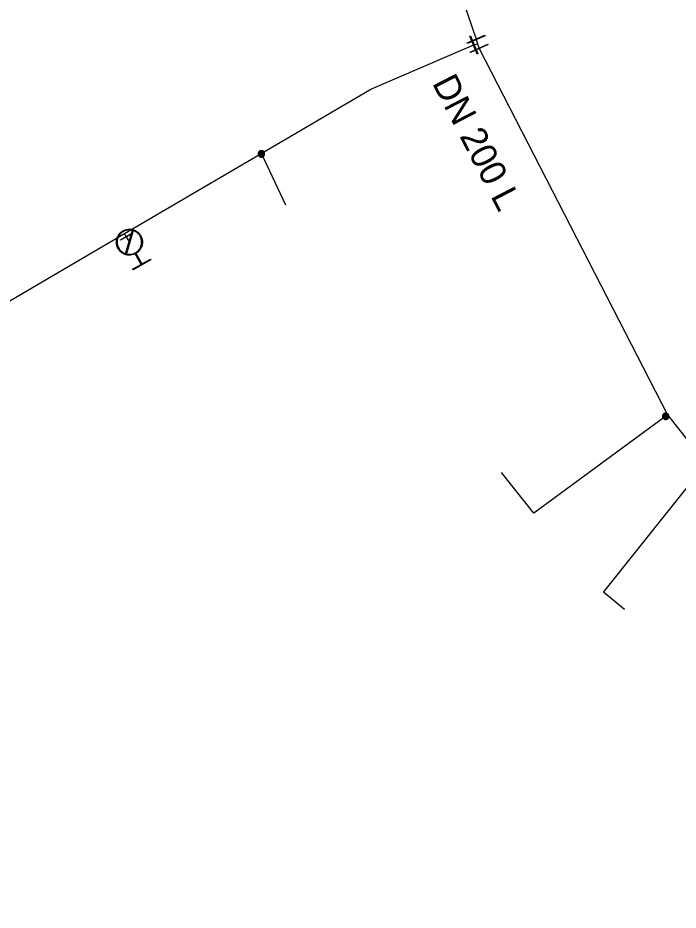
# Model space of a CAD drawing. Extents: x -832382 to -831581, y -1074670 to -1074251.
# Drawn here: x -831734.8 to -831683.8, y -1074502.9 to -1074434.1 of the extents above; entities that cross this region are included whole.
import ezdxf

# ---------------------------------------------------------------- set-up
doc = ezdxf.new("R2010")
doc.units = 0
for name, color, linetype in [('Hyd-odbočka', 7, 'Continuous'), ('Hyd-šoupě', 7, 'Continuous'), ('Hydrant', 7, 'Continuous'), ('Přípojka vodovodu', 7, 'Continuous'), ('Přípojkový uzávěr', 7, 'Continuous'), ('Roz-řad', 7, 'Continuous'), ('Roz-řad-popis základní', 7, 'Continuous'), ('Řad-šoupě', 7, 'Continuous')]:
    doc.layers.add(name, color=color, linetype=linetype)

msp = doc.modelspace()

# ---------------------------------------------------------------- linework, layer by layer
at = {"layer": 'Hyd-odbočka'}
for q in [(-831726.547, -1074450.718), (-831726.16, -1074451.38)]:
    msp.add_line((-831726.41, -1074450.96), q, dxfattribs=at)
at = {"layer": 'Hyd-šoupě'}
msp.add_lwpolyline([(-831726.853, -1074451.192), (-831725.982, -1074450.7), (-831725.967, -1074450.727), (-831726.837, -1074451.219), (-831726.853, -1074451.192)], dxfattribs=at)
at = {"layer": 'Hydrant'}
for points in [[(-831726.451, -1074452.273), (-831725.928, -1074450.468)], [(-831725.869, -1074450.487), (-831726.393, -1074452.29)], [(-831725.651, -1074452.241), (-831725.199, -1074453.063), (-831724.542, -1074452.702), (-831724.512, -1074452.756), (-831725.881, -1074453.509), (-831725.911, -1074453.454), (-831725.254, -1074453.093), (-831725.706, -1074452.271)]]:
    msp.add_lwpolyline(points, dxfattribs=at)
for points in [[(-831725.706, -1074452.271), (-831725.917, -1074452.378), (-831726.172, -1074452.38), (-831726.443, -1074452.382), (-831726.676, -1074452.237), (-831726.91, -1074452.091), (-831727.036, -1074451.862), (-831727.161, -1074451.634), (-831727.161, -1074451.362), (-831727.16, -1074451.089), (-831727.015, -1074450.859), (-831726.869, -1074450.629), (-831726.642, -1074450.504), (-831726.414, -1074450.379), (-831726.142, -1074450.379), (-831725.869, -1074450.38), (-831725.639, -1074450.525), (-831725.409, -1074450.671), (-831725.284, -1074450.898), (-831725.158, -1074451.128), (-831725.16, -1074451.403), (-831725.162, -1074451.679), (-831725.309, -1074451.906), (-831725.446, -1074452.12), (-831725.651, -1074452.241)], [(-831725.928, -1074450.468), (-831726.031, -1074450.442), (-831726.142, -1074450.443), (-831726.398, -1074450.441), (-831726.612, -1074450.558), (-831726.826, -1074450.676), (-831726.962, -1074450.892), (-831727.098, -1074451.109), (-831727.099, -1074451.363), (-831727.099, -1074451.618), (-831726.982, -1074451.832), (-831726.863, -1074452.047), (-831726.644, -1074452.183), (-831726.55, -1074452.24), (-831726.451, -1074452.273)], [(-831726.393, -1074452.29), (-831726.284, -1074452.318), (-831726.171, -1074452.317), (-831725.916, -1074452.315), (-831725.708, -1074452.202), (-831725.501, -1074452.088), (-831725.363, -1074451.873), (-831725.224, -1074451.659), (-831725.222, -1074451.402), (-831725.22, -1074451.144), (-831725.338, -1074450.928), (-831725.456, -1074450.714), (-831725.673, -1074450.58), (-831725.766, -1074450.519), (-831725.869, -1074450.487)]]:
    msp.add_open_spline(points, degree=3, dxfattribs=at)
at = {"layer": 'Přípojka vodovodu'}
for points in [[(-831715.985, -1074444.538), (-831715.97, -1074444.57), (-831714.12, -1074448.5)], [(-831684.613, -1074464.713), (-831684.753, -1074464.816), (-831694.927, -1074472.301), (-831697.436, -1074469.153)], [(-831681.645, -1074468.448), (-831681.71, -1074468.53), (-831689.553, -1074478.367), (-831687.925, -1074479.696)]]:
    msp.add_lwpolyline(points, dxfattribs=at)
at = {"layer": 'Přípojkový uzávěr'}
for points in [[(-831715.97, -1074444.32), (-831715.907, -1074444.32), (-831715.847, -1074444.352), (-831715.788, -1074444.384), (-831715.754, -1074444.445), (-831715.72, -1074444.505), (-831715.72, -1074444.57), (-831715.72, -1074444.635), (-831715.753, -1074444.695), (-831715.786, -1074444.754), (-831715.845, -1074444.787), (-831715.905, -1074444.82), (-831715.97, -1074444.82), (-831716.035, -1074444.82), (-831716.095, -1074444.787), (-831716.154, -1074444.754), (-831716.187, -1074444.695), (-831716.22, -1074444.635), (-831716.22, -1074444.57), (-831716.22, -1074444.505), (-831716.186, -1074444.445), (-831716.153, -1074444.384), (-831716.093, -1074444.352), (-831716.033, -1074444.32), (-831715.97, -1074444.32)], [(-831715.97, -1074444.343), (-831716.027, -1074444.343), (-831716.082, -1074444.373), (-831716.136, -1074444.402), (-831716.166, -1074444.456), (-831716.197, -1074444.511), (-831716.197, -1074444.57), (-831716.197, -1074444.629), (-831716.167, -1074444.683), (-831716.137, -1074444.737), (-831716.083, -1074444.767), (-831716.029, -1074444.797), (-831715.97, -1074444.797), (-831715.911, -1074444.797), (-831715.857, -1074444.767), (-831715.803, -1074444.737), (-831715.773, -1074444.683), (-831715.743, -1074444.629), (-831715.743, -1074444.57), (-831715.743, -1074444.511), (-831715.774, -1074444.456), (-831715.805, -1074444.402), (-831715.859, -1074444.373), (-831715.913, -1074444.343), (-831715.97, -1074444.343)], [(-831715.97, -1074444.361), (-831715.917, -1074444.361), (-831715.867, -1074444.388), (-831715.817, -1074444.414), (-831715.789, -1074444.465), (-831715.761, -1074444.515), (-831715.761, -1074444.57), (-831715.761, -1074444.625), (-831715.788, -1074444.674), (-831715.815, -1074444.724), (-831715.866, -1074444.752), (-831715.916, -1074444.779), (-831715.97, -1074444.779), (-831716.024, -1074444.779), (-831716.074, -1074444.752), (-831716.125, -1074444.724), (-831716.152, -1074444.674), (-831716.179, -1074444.625), (-831716.179, -1074444.57), (-831716.179, -1074444.515), (-831716.151, -1074444.465), (-831716.123, -1074444.414), (-831716.073, -1074444.388), (-831716.023, -1074444.361), (-831715.97, -1074444.361)], [(-831715.97, -1074444.383), (-831716.049, -1074444.383), (-831716.103, -1074444.437), (-831716.157, -1074444.492), (-831716.157, -1074444.57), (-831716.157, -1074444.648), (-831716.103, -1074444.703), (-831716.048, -1074444.758), (-831715.97, -1074444.758), (-831715.892, -1074444.758), (-831715.837, -1074444.703), (-831715.782, -1074444.648), (-831715.782, -1074444.57), (-831715.782, -1074444.492), (-831715.837, -1074444.437), (-831715.892, -1074444.383), (-831715.97, -1074444.383)], [(-831715.97, -1074444.405), (-831715.902, -1074444.405), (-831715.854, -1074444.453), (-831715.806, -1074444.501), (-831715.806, -1074444.57), (-831715.806, -1074444.638), (-831715.854, -1074444.686), (-831715.902, -1074444.734), (-831715.97, -1074444.734), (-831716.039, -1074444.734), (-831716.087, -1074444.686), (-831716.135, -1074444.638), (-831716.135, -1074444.57), (-831716.135, -1074444.501), (-831716.087, -1074444.453), (-831716.039, -1074444.405), (-831715.97, -1074444.405)], [(-831715.97, -1074444.425), (-831716.031, -1074444.425), (-831716.073, -1074444.467), (-831716.115, -1074444.51), (-831716.115, -1074444.57), (-831716.115, -1074444.629), (-831716.073, -1074444.672), (-831716.031, -1074444.714), (-831715.97, -1074444.714), (-831715.911, -1074444.714), (-831715.868, -1074444.672), (-831715.826, -1074444.629), (-831715.826, -1074444.57), (-831715.826, -1074444.51), (-831715.868, -1074444.467), (-831715.91, -1074444.425), (-831715.97, -1074444.425)], [(-831715.97, -1074444.445), (-831715.918, -1074444.445), (-831715.881, -1074444.482), (-831715.845, -1074444.518), (-831715.845, -1074444.57), (-831715.845, -1074444.622), (-831715.882, -1074444.659), (-831715.918, -1074444.695), (-831715.97, -1074444.695), (-831716.022, -1074444.695), (-831716.058, -1074444.659), (-831716.095, -1074444.622), (-831716.095, -1074444.57), (-831716.095, -1074444.518), (-831716.059, -1074444.482), (-831716.022, -1074444.445), (-831715.97, -1074444.445)], [(-831715.97, -1074444.468), (-831716.012, -1074444.468), (-831716.042, -1074444.498), (-831716.072, -1074444.528), (-831716.072, -1074444.57), (-831716.072, -1074444.612), (-831716.042, -1074444.642), (-831716.012, -1074444.671), (-831715.97, -1074444.671), (-831715.928, -1074444.671), (-831715.898, -1074444.642), (-831715.869, -1074444.612), (-831715.869, -1074444.57), (-831715.869, -1074444.528), (-831715.898, -1074444.498), (-831715.928, -1074444.468), (-831715.97, -1074444.468)], [(-831715.97, -1074444.486), (-831715.935, -1074444.486), (-831715.911, -1074444.51), (-831715.886, -1074444.535), (-831715.886, -1074444.57), (-831715.886, -1074444.605), (-831715.911, -1074444.629), (-831715.935, -1074444.654), (-831715.97, -1074444.654), (-831716.005, -1074444.654), (-831716.03, -1074444.629), (-831716.054, -1074444.605), (-831716.054, -1074444.57), (-831716.054, -1074444.535), (-831716.03, -1074444.51), (-831716.005, -1074444.486), (-831715.97, -1074444.486)], [(-831715.97, -1074444.508), (-831715.996, -1074444.508), (-831716.014, -1074444.526), (-831716.032, -1074444.544), (-831716.032, -1074444.57), (-831716.032, -1074444.596), (-831716.014, -1074444.614), (-831715.996, -1074444.633), (-831715.97, -1074444.633), (-831715.944, -1074444.633), (-831715.926, -1074444.614), (-831715.907, -1074444.596), (-831715.907, -1074444.57), (-831715.907, -1074444.544), (-831715.926, -1074444.526), (-831715.944, -1074444.508), (-831715.97, -1074444.508)], [(-831715.97, -1074444.531), (-831715.954, -1074444.531), (-831715.942, -1074444.542), (-831715.931, -1074444.553), (-831715.931, -1074444.57), (-831715.931, -1074444.586), (-831715.942, -1074444.598), (-831715.954, -1074444.609), (-831715.97, -1074444.609), (-831715.986, -1074444.609), (-831715.998, -1074444.598), (-831716.009, -1074444.586), (-831716.009, -1074444.57), (-831716.009, -1074444.553), (-831715.998, -1074444.542), (-831715.986, -1074444.531), (-831715.97, -1074444.531)], [(-831715.97, -1074444.547), (-831715.98, -1074444.547), (-831715.987, -1074444.553), (-831715.994, -1074444.56), (-831715.994, -1074444.57), (-831715.994, -1074444.58), (-831715.987, -1074444.587), (-831715.98, -1074444.593), (-831715.97, -1074444.593), (-831715.96, -1074444.593), (-831715.954, -1074444.587), (-831715.947, -1074444.58), (-831715.947, -1074444.57), (-831715.947, -1074444.56), (-831715.954, -1074444.553), (-831715.96, -1074444.547), (-831715.97, -1074444.547)], [(-831684.753, -1074464.566), (-831684.69, -1074464.566), (-831684.63, -1074464.598), (-831684.571, -1074464.631), (-831684.537, -1074464.691), (-831684.503, -1074464.751), (-831684.503, -1074464.816), (-831684.503, -1074464.881), (-831684.536, -1074464.941), (-831684.569, -1074465), (-831684.629, -1074465.033), (-831684.688, -1074465.066), (-831684.753, -1074465.066), (-831684.818, -1074465.066), (-831684.878, -1074465.033), (-831684.937, -1074465), (-831684.97, -1074464.941), (-831685.003, -1074464.881), (-831685.003, -1074464.816), (-831685.003, -1074464.751), (-831684.969, -1074464.691), (-831684.936, -1074464.631), (-831684.876, -1074464.598), (-831684.816, -1074464.566), (-831684.753, -1074464.566)], [(-831684.753, -1074464.59), (-831684.81, -1074464.59), (-831684.865, -1074464.619), (-831684.919, -1074464.648), (-831684.949, -1074464.703), (-831684.98, -1074464.757), (-831684.98, -1074464.816), (-831684.98, -1074464.875), (-831684.95, -1074464.929), (-831684.92, -1074464.983), (-831684.866, -1074465.013), (-831684.812, -1074465.043), (-831684.753, -1074465.043), (-831684.694, -1074465.043), (-831684.64, -1074465.013), (-831684.586, -1074464.983), (-831684.556, -1074464.929), (-831684.526, -1074464.875), (-831684.526, -1074464.816), (-831684.526, -1074464.757), (-831684.557, -1074464.703), (-831684.588, -1074464.648), (-831684.642, -1074464.619), (-831684.696, -1074464.59), (-831684.753, -1074464.59)], [(-831684.753, -1074464.607), (-831684.7, -1074464.607), (-831684.65, -1074464.634), (-831684.6, -1074464.661), (-831684.572, -1074464.711), (-831684.544, -1074464.762), (-831684.544, -1074464.816), (-831684.544, -1074464.871), (-831684.571, -1074464.921), (-831684.598, -1074464.971), (-831684.649, -1074464.998), (-831684.699, -1074465.026), (-831684.753, -1074465.026), (-831684.807, -1074465.026), (-831684.858, -1074464.998), (-831684.908, -1074464.971), (-831684.935, -1074464.921), (-831684.962, -1074464.871), (-831684.962, -1074464.816), (-831684.962, -1074464.762), (-831684.934, -1074464.711), (-831684.906, -1074464.661), (-831684.856, -1074464.634), (-831684.806, -1074464.607), (-831684.753, -1074464.607)], [(-831684.754, -1074464.629), (-831684.832, -1074464.629), (-831684.886, -1074464.684), (-831684.941, -1074464.739), (-831684.941, -1074464.816), (-831684.941, -1074464.894), (-831684.886, -1074464.949), (-831684.831, -1074465.004), (-831684.754, -1074465.004), (-831684.675, -1074465.004), (-831684.62, -1074464.949), (-831684.566, -1074464.894), (-831684.566, -1074464.816), (-831684.566, -1074464.739), (-831684.62, -1074464.684), (-831684.675, -1074464.629), (-831684.754, -1074464.629)], [(-831684.754, -1074464.652), (-831684.685, -1074464.652), (-831684.637, -1074464.7), (-831684.589, -1074464.748), (-831684.589, -1074464.816), (-831684.589, -1074464.884), (-831684.637, -1074464.932), (-831684.685, -1074464.98), (-831684.754, -1074464.98), (-831684.822, -1074464.98), (-831684.87, -1074464.932), (-831684.918, -1074464.884), (-831684.918, -1074464.816), (-831684.918, -1074464.748), (-831684.87, -1074464.7), (-831684.822, -1074464.652), (-831684.754, -1074464.652)], [(-831684.754, -1074464.671), (-831684.814, -1074464.671), (-831684.856, -1074464.714), (-831684.898, -1074464.756), (-831684.898, -1074464.816), (-831684.898, -1074464.876), (-831684.856, -1074464.918), (-831684.814, -1074464.96), (-831684.754, -1074464.96), (-831684.694, -1074464.96), (-831684.651, -1074464.918), (-831684.609, -1074464.876), (-831684.609, -1074464.816), (-831684.609, -1074464.756), (-831684.651, -1074464.714), (-831684.693, -1074464.671), (-831684.754, -1074464.671)], [(-831684.753, -1074464.691), (-831684.701, -1074464.691), (-831684.664, -1074464.728), (-831684.628, -1074464.764), (-831684.628, -1074464.816), (-831684.628, -1074464.868), (-831684.665, -1074464.905), (-831684.701, -1074464.941), (-831684.753, -1074464.941), (-831684.805, -1074464.941), (-831684.841, -1074464.905), (-831684.878, -1074464.868), (-831684.878, -1074464.816), (-831684.878, -1074464.764), (-831684.842, -1074464.728), (-831684.806, -1074464.691), (-831684.753, -1074464.691)], [(-831684.753, -1074464.714), (-831684.796, -1074464.714), (-831684.825, -1074464.744), (-831684.855, -1074464.774), (-831684.855, -1074464.816), (-831684.855, -1074464.858), (-831684.825, -1074464.888), (-831684.796, -1074464.918), (-831684.753, -1074464.918), (-831684.711, -1074464.918), (-831684.681, -1074464.888), (-831684.652, -1074464.858), (-831684.652, -1074464.816), (-831684.652, -1074464.774), (-831684.681, -1074464.744), (-831684.711, -1074464.714), (-831684.753, -1074464.714)], [(-831684.753, -1074464.732), (-831684.718, -1074464.732), (-831684.694, -1074464.756), (-831684.669, -1074464.781), (-831684.669, -1074464.816), (-831684.669, -1074464.851), (-831684.694, -1074464.876), (-831684.718, -1074464.9), (-831684.753, -1074464.9), (-831684.788, -1074464.9), (-831684.813, -1074464.876), (-831684.837, -1074464.851), (-831684.837, -1074464.816), (-831684.837, -1074464.781), (-831684.813, -1074464.756), (-831684.788, -1074464.732), (-831684.753, -1074464.732)], [(-831684.753, -1074464.754), (-831684.779, -1074464.754), (-831684.797, -1074464.772), (-831684.816, -1074464.79), (-831684.816, -1074464.816), (-831684.816, -1074464.842), (-831684.797, -1074464.86), (-831684.779, -1074464.879), (-831684.753, -1074464.879), (-831684.727, -1074464.879), (-831684.709, -1074464.86), (-831684.691, -1074464.842), (-831684.691, -1074464.816), (-831684.691, -1074464.79), (-831684.709, -1074464.772), (-831684.727, -1074464.754), (-831684.753, -1074464.754)], [(-831684.753, -1074464.777), (-831684.737, -1074464.777), (-831684.725, -1074464.788), (-831684.714, -1074464.8), (-831684.714, -1074464.816), (-831684.714, -1074464.832), (-831684.725, -1074464.844), (-831684.737, -1074464.855), (-831684.753, -1074464.855), (-831684.769, -1074464.855), (-831684.781, -1074464.844), (-831684.792, -1074464.832), (-831684.792, -1074464.816), (-831684.792, -1074464.8), (-831684.781, -1074464.788), (-831684.769, -1074464.777), (-831684.753, -1074464.777)], [(-831684.753, -1074464.793), (-831684.763, -1074464.793), (-831684.77, -1074464.799), (-831684.777, -1074464.806), (-831684.777, -1074464.816), (-831684.777, -1074464.826), (-831684.77, -1074464.833), (-831684.763, -1074464.84), (-831684.753, -1074464.84), (-831684.743, -1074464.84), (-831684.737, -1074464.833), (-831684.73, -1074464.826), (-831684.73, -1074464.816), (-831684.73, -1074464.806), (-831684.737, -1074464.799), (-831684.743, -1074464.793), (-831684.753, -1074464.793)]]:
    msp.add_open_spline(points, degree=3, dxfattribs=at)
at = {"layer": 'Roz-řad'}
for p, q in [((-831699.39, -1074435.73), (-831699.275, -1074436.08)), ((-831699.57, -1074436.17), (-831699.275, -1074436.08)), ((-831699.275, -1074436.08), (-831699.16, -1074436.43))]:
    msp.add_line(p, q, dxfattribs=at)
for points in [[(-831710.74, -1074402.57), (-831709.938, -1074404.913), (-831709.653, -1074405.745), (-831699.39, -1074435.73)], [(-831778.085, -1074503.291), (-831772.842, -1074496.164), (-831771.36, -1074494.15), (-831763.76, -1074483.99), (-831763.769, -1074484.049), (-831763.194, -1074483.398), (-831747.84, -1074465.99), (-831737.66, -1074457.22), (-831726.547, -1074450.718), (-831715.985, -1074444.538), (-831707.51, -1074439.58), (-831699.57, -1074436.17)], [(-831699.16, -1074436.43), (-831684.613, -1074464.713), (-831681.645, -1074468.448), (-831680.42, -1074469.611), (-831670.1, -1074478.783)]]:
    msp.add_lwpolyline(points, dxfattribs=at)
at = {"layer": 'Řad-šoupě'}
for points in [[(-831698.693, -1074435.453), (-831700.069, -1074436.05), (-831700.088, -1074436.007), (-831698.712, -1074435.41), (-831698.693, -1074435.453)], [(-831699.314, -1074436.875), (-831699.87, -1074435.482), (-831699.827, -1074435.465), (-831699.27, -1074436.858), (-831699.314, -1074436.875)], [(-831699.854, -1074436.717), (-831698.486, -1074436.101), (-831698.467, -1074436.144), (-831699.834, -1074436.76), (-831699.854, -1074436.717)]]:
    msp.add_lwpolyline(points, dxfattribs=at)

# ---------------------------------------------------------------- texts
at = {"layer": 'Roz-řad-popis základní'}
msp.add_text('DN 200 L', height=2, rotation=297.41271, dxfattribs=at).set_placement((-831702.82, -1074439.104))

doc.saveas('drawing.dxf')
